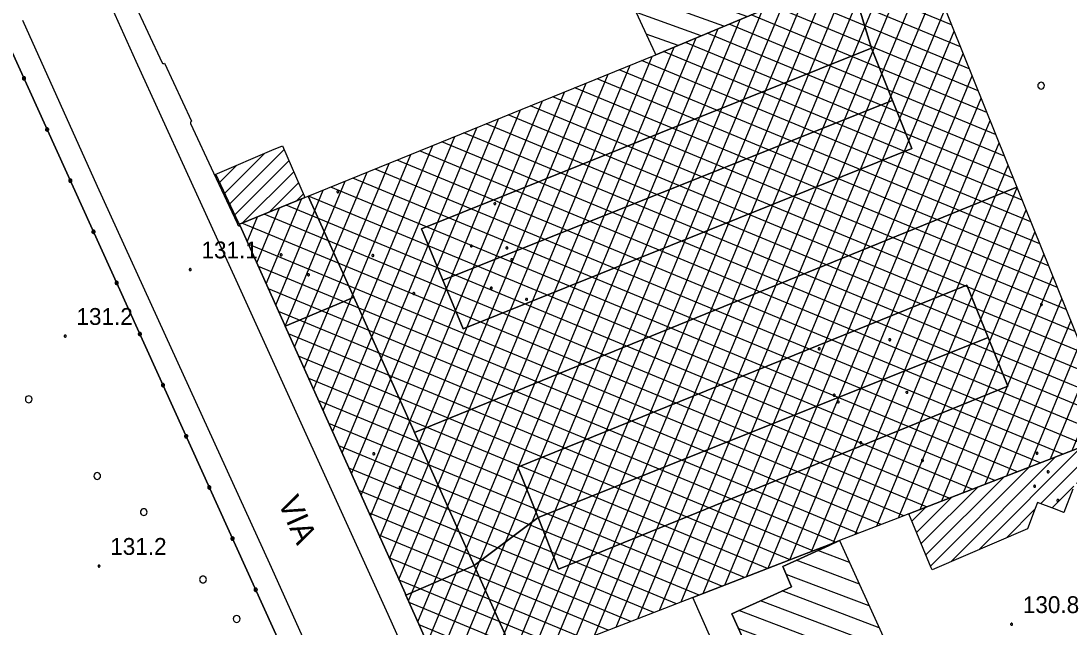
# Model space of a CAD drawing. Extents: x 513373 to 514978, y 5038576 to 5040180.
# Drawn here: x 513457.4 to 513550.7, y 5038827.3 to 5038881.2 of the extents above; entities that cross this region are included whole.
import ezdxf

# ---------------------------------------------------------------- set-up
doc = ezdxf.new("R2010")
doc.units = 0
for name, color, linetype in [('B1211', 7, 'Continuous'), ('C1131', 7, 'Continuous'), ('C12211', 7, 'Continuous'), ('C1228', 7, 'Continuous'), ('C21111', 7, 'Continuous'), ('C211113', 7, 'Continuous'), ('C21195', 7, 'Continuous'), ('C2911', 7, 'Continuous'), ('CAMP_C12211', 7, 'Continuous'), ('CAMP_C1228', 7, 'Continuous'), ('CAMP_C21111', 7, 'Continuous'), ('CAMP_C21195', 7, 'Continuous'), ('Default', 7, 'Continuous'), ('F12107', 7, 'Continuous'), ('F12131', 7, 'Continuous'), ('F12132', 7, 'Continuous'), ('G4315', 7, 'Continuous'), ('TOP500', 7, 'Continuous'), ('TOP920', 7, 'Continuous')]:
    doc.layers.add(name, color=color, linetype=linetype)

# ---------------------------------------------------------------- blocks, each defined once
blk = doc.blocks.new('CAMP_172EE3B1')
at = {"layer": 'CAMP_C1228'}
for p, q in [((-4.116, -26.219), (20.728, 33.759)), ((-6.049, -26.968), (18.763, 32.934)), ((21.465, 32.505), (19.59, 33.281)), ((-7.983, -27.718), (16.798, 32.11)), ((-2.182, -25.47), (21.646, 32.055)), ((22.251, 30.556), (17.643, 32.464)), ((-9.917, -28.467), (14.833, 31.285)), ((23.823, 26.658), (13.749, 30.83)), ((23.037, 28.607), (15.696, 31.647)), ((-11.851, -29.216), (12.867, 30.46)), ((-0.248, -24.721), (22.447, 30.069)), ((24.609, 24.708), (11.802, 30.013)), ((-13.785, -29.965), (10.902, 29.635)), ((25.394, 22.759), (9.855, 29.196)), ((-15.766, -30.829), (8.937, 28.811)), ((1.686, -23.971), (23.248, 28.083)), ((26.18, 20.81), (7.908, 28.379)), ((-19.779, -32.677), (5.007, 27.161)), ((-17.773, -31.753), (6.972, 27.986)), ((26.966, 18.861), (5.961, 27.562)), ((-21.185, -32.152), (3.041, 26.336)), ((27.752, 16.912), (4.014, 26.745)), ((-22.028, -30.267), (1.076, 25.512)), ((28.538, 14.963), (2.067, 25.927)), ((3.62, -23.222), (24.049, 26.097)), ((-22.871, -28.382), (-0.889, 24.687)), ((30.11, 11.065), (-1.827, 24.293)), ((29.324, 13.014), (0.12, 25.11)), ((-23.714, -26.497), (-2.852, 23.867)), ((30.896, 9.116), (-3.794, 23.484)), ((5.554, -22.473), (24.85, 24.111)), ((-24.557, -24.612), (-4.805, 23.073)), ((31.681, 7.167), (-5.771, 22.68)), ((-26.245, -20.85), (-8.71, 21.484)), ((-25.401, -22.73), (-6.757, 22.279)), ((32.467, 5.217), (-7.749, 21.875)), ((7.488, -21.723), (25.65, 22.124)), ((-27.09, -18.969), (-10.662, 20.69)), ((33.253, 3.268), (-9.726, 21.071)), ((-27.934, -17.088), (-12.615, 19.896)), ((34.039, 1.319), (-11.704, 20.267)), ((9.422, -20.974), (26.451, 20.138)), ((-28.779, -15.207), (-14.568, 19.102)), ((34.825, -0.63), (-13.681, 19.462)), ((-29.623, -13.326), (-16.52, 18.307)), ((36.396, -4.528), (-17.637, 17.853)), ((35.61, -2.579), (-15.659, 18.658)), ((11.356, -20.225), (27.252, 18.152)), ((-30.468, -11.445), (-18.473, 17.513)), ((37.182, -6.477), (-19.614, 17.049)), ((-32.157, -7.683), (-22.378, 15.924)), ((-31.312, -9.564), (-20.425, 16.719)), ((37.968, -8.426), (-21.592, 16.244)), ((13.29, -19.475), (28.053, 16.166)), ((-33.001, -5.802), (-24.331, 15.13)), ((37.8, -9.98), (-23.569, 15.44)), ((-33.846, -3.921), (-26.283, 14.336)), ((35.775, -10.765), (-25.547, 14.635)), ((15.224, -18.726), (28.854, 14.179)), ((-34.69, -2.04), (-28.236, 13.542)), ((33.75, -11.55), (-27.524, 13.831)), ((-35.535, -0.159), (-30.188, 12.747)), ((29.699, -13.119), (-31.48, 12.222)), ((31.724, -12.334), (-29.502, 13.026)), ((17.158, -17.977), (29.655, 12.193)), ((-36.38, 1.719), (-32.141, 11.953)), ((27.673, -13.904), (-33.457, 11.418)), ((-38.071, 5.476), (-36.046, 10.364)), ((-37.226, 3.598), (-34.094, 11.159)), ((25.648, -14.688), (-35.435, 10.613)), ((-38.917, 7.354), (-37.999, 9.57)), ((23.623, -15.473), (-37.412, 9.809)), ((19.092, -17.228), (30.456, 10.207)), ((21.597, -16.257), (-39.39, 9.004)), ((21.026, -16.479), (31.256, 8.22)), ((19.572, -17.042), (-38.822, 7.146)), ((22.96, -15.73), (32.057, 6.234)), ((17.546, -17.827), (-37.924, 5.15)), ((24.893, -14.98), (32.858, 4.248)), ((15.521, -18.611), (-37.026, 3.154)), ((26.827, -14.231), (33.659, 2.261)), ((13.495, -19.396), (-36.128, 1.159)), ((28.761, -13.482), (34.46, 0.275)), ((11.47, -20.181), (-35.231, -0.837)), ((30.695, -12.733), (35.261, -1.711)), ((9.445, -20.965), (-34.335, -2.831)), ((32.629, -11.984), (36.061, -3.697)), ((7.419, -21.75), (-33.44, -4.826)), ((34.563, -11.234), (36.862, -5.684)), ((5.394, -22.535), (-32.544, -6.82)), ((36.497, -10.485), (37.663, -7.67)), ((3.369, -23.319), (-31.649, -8.815)), ((38.431, -9.736), (38.464, -9.656)), ((1.344, -24.104), (-30.753, -10.809)), ((-0.682, -24.889), (-29.858, -12.804)), ((-2.707, -25.673), (-28.962, -14.798)), ((-4.732, -26.458), (-28.067, -16.793)), ((-6.758, -27.243), (-27.171, -18.787)), ((-8.783, -28.027), (-26.276, -20.782)), ((-10.808, -28.812), (-25.38, -22.776)), ((-12.834, -29.597), (-24.486, -24.77)), ((-14.826, -30.395), (-23.595, -26.763)), ((-16.681, -31.25), (-22.704, -28.755)), ((-18.537, -32.105), (-21.813, -30.748)), ((-20.393, -32.96), (-20.922, -32.741))]:
    blk.add_line(p, q, dxfattribs=at)
blk = doc.blocks.new('CAMP_F478D1B5')
at = {"layer": 'CAMP_C12211'}
for p, q in [((-13.389, 14.386), (-15.321, 15.082)), ((17.239, 14.519), (14.832, 15.385)), ((-12.639, 12.522), (-17.408, 14.238)), ((18.129, 12.604), (12.839, 14.509)), ((-11.889, 10.657), (-19.494, 13.395)), ((19.018, 10.69), (10.846, 13.632)), ((-11.89, 9.064), (-21.581, 12.552)), ((-13.23, 7.952), (-23.667, 11.709)), ((19.906, 8.776), (11.157, 11.926)), ((-12.368, 6.047), (-24.001, 10.235)), ((20.795, 6.862), (12.015, 10.023)), ((-11.505, 4.142), (-23.152, 8.335)), ((21.684, 4.947), (12.873, 8.12)), ((-10.643, 2.237), (-22.303, 6.435)), ((22.574, 3.033), (13.73, 6.217)), ((-9.78, 0.333), (-21.471, 4.542)), ((23.463, 1.118), (14.588, 4.313)), ((-8.918, -1.572), (-20.705, 2.671)), ((24.352, -0.796), (15.446, 2.41)), ((25.242, -2.71), (15.044, 0.961)), ((-8.055, -3.477), (-19.886, 0.782)), ((23.989, -3.854), (12.958, 0.118)), ((21.876, -4.687), (10.872, -0.726)), ((-7.193, -5.382), (-19.003, -1.13)), ((19.763, -5.521), (8.786, -1.569)), ((17.65, -6.354), (6.7, -2.412)), ((-6.33, -7.286), (-18.12, -3.042)), ((15.537, -7.188), (4.615, -3.256)), ((13.423, -8.021), (2.529, -4.099)), ((3.165, -12.299), (-17.237, -4.954)), ((11.344, -8.867), (0.443, -4.942)), ((9.299, -9.725), (-1.643, -5.786)), ((1.121, -13.157), (-16.353, -6.866)), ((7.255, -10.583), (-3.728, -6.629)), ((5.21, -11.441), (-5.814, -7.472)), ((-0.924, -14.016), (-15.47, -8.779)), ((-2.969, -14.874), (-14.587, -10.691)), ((-5.014, -15.732), (-13.704, -12.603)), ((-7.058, -16.59), (-12.821, -14.515)), ((-9.103, -17.448), (-11.938, -16.427))]:
    blk.add_line(p, q, dxfattribs=at)
blk = doc.blocks.new('CAMP_EDF7B2BA')
at = {"layer": 'CAMP_C12211'}
for p, q in [((-15.013, 46.563), (-15.029, 46.569)), ((-13.253, 42.69), (-18.881, 44.817)), ((-14.133, 44.627), (-16.955, 45.693)), ((-12.373, 40.754), (-19.77, 43.55)), ((-11.492, 38.818), (-20.148, 42.089)), ((-10.612, 36.882), (-22.07, 41.212)), ((-9.732, 34.946), (-23.992, 40.335)), ((-8.851, 33.01), (-24.047, 38.752)), ((-7.971, 31.074), (-23.166, 36.815)), ((-7.091, 29.137), (-22.285, 34.879)), ((-6.211, 27.201), (-21.405, 32.943)), ((-5.33, 25.265), (-20.524, 31.006)), ((-4.45, 23.329), (-19.644, 29.07)), ((-3.57, 21.393), (-18.763, 27.134)), ((-2.689, 19.457), (-17.882, 25.198)), ((-1.809, 17.521), (-17.002, 23.261)), ((-0.929, 15.584), (-16.121, 21.325)), ((-0.049, 13.648), (-15.24, 19.389)), ((0.832, 11.712), (-14.359, 17.452)), ((1.712, 9.776), (-13.479, 15.516)), ((2.592, 7.84), (-12.598, 13.58)), ((3.473, 5.904), (-11.717, 11.643)), ((4.353, 3.967), (-10.837, 9.707)), ((5.233, 2.031), (-9.956, 7.771)), ((6.113, 0.095), (-9.075, 5.834)), ((6.994, -1.841), (-8.194, 3.898)), ((7.874, -3.777), (-7.314, 1.962)), ((8.754, -5.713), (-6.433, 0.026)), ((9.635, -7.649), (-5.552, -1.911)), ((10.515, -9.586), (-4.672, -3.847)), ((11.394, -11.521), (-3.791, -5.783)), ((12.272, -13.457), (-2.91, -7.72)), ((13.15, -15.392), (-2.029, -9.656)), ((14.028, -17.327), (-1.149, -11.592)), ((14.906, -19.263), (-0.268, -13.529)), ((15.785, -21.198), (0.613, -15.465)), ((16.663, -23.133), (1.493, -17.401)), ((17.541, -25.069), (2.374, -19.338)), ((18.419, -27.004), (3.255, -21.274)), ((19.297, -28.939), (4.135, -23.21)), ((20.175, -30.874), (5.016, -25.146)), ((21.058, -32.812), (5.897, -27.083)), ((21.945, -34.75), (6.777, -29.019)), ((22.83, -36.688), (7.658, -30.955)), ((23.713, -38.625), (8.539, -32.892)), ((24.596, -40.563), (9.419, -34.828)), ((25.479, -42.5), (10.3, -36.764)), ((24.118, -43.589), (11.181, -38.7)), ((22.189, -44.464), (12.061, -40.637)), ((20.26, -45.338), (12.942, -42.573)), ((18.331, -46.213), (13.823, -44.509)), ((16.403, -47.088), (14.704, -46.446))]:
    blk.add_line(p, q, dxfattribs=at)
blk = doc.blocks.new('CAMP_2F9B1B2A')
at = {"layer": 'CAMP_C21111'}
for p, q in [((-3.433, -0.605), (0.103, 2.931)), ((-2.983, -1.568), (1.853, 3.267)), ((-3.884, 0.358), (-2.359, 1.884)), ((-2.532, -2.532), (2.277, 2.277)), ((-1.857, -3.271), (2.701, 1.287)), ((0.527, -2.301), (3.125, 0.297)), ((2.911, -1.331), (3.55, -0.693))]:
    blk.add_line(p, q, dxfattribs=at)
blk = doc.blocks.new('CAMP_9FC88B0B')
at = {"layer": 'CAMP_C21195'}
for p, q in [((7.267, 1.118), (14.947, 8.798)), ((8.795, 1.232), (16.636, 9.073)), ((6.252, 1.517), (12.544, 7.809)), ((11.261, 2.284), (17.1, 8.122)), ((3.079, -0.241), (10.141, 6.82)), ((13.728, 3.336), (17.563, 7.171)), ((2.062, 0.156), (7.737, 5.831)), ((16.194, 4.389), (18.026, 6.221)), ((-1.174, -1.666), (5.334, 4.842)), ((-2.191, -1.269), (2.931, 3.853)), ((-5.38, -3.043), (0.56, 2.896)), ((-10.906, -7.155), (-1.749, 2.002)), ((-13.386, -8.221), (-4.057, 1.108)), ((-15.192, -8.613), (-6.366, 0.213)), ((-15.608, -7.614), (-8.674, -0.681)), ((-0.158, -2.064), (1.149, -0.757)), ((4.096, -0.639), (4.402, -0.332)), ((-16.023, -6.616), (-10.983, -1.575)), ((-4.362, -3.44), (-2.421, -1.498)), ((-16.439, -5.617), (-13.292, -2.47)), ((-16.854, -4.618), (-15.6, -3.364)), ((-8.427, -6.09), (-5.895, -3.558)), ((-3.344, -3.836), (-3.322, -3.814))]:
    blk.add_line(p, q, dxfattribs=at)
blk = doc.blocks.new('03080200')
at = {"layer": 'Default'}
for p, q in [((-0.139, 0.046), (-0.146, 0)), ((-0.146, 0), (-0.139, -0.046)), ((-0.118, 0.086), (-0.139, 0.046)), ((-0.086, 0.118), (-0.118, 0.086)), ((-0.046, 0.139), (-0.086, 0.118)), ((0, 0.146), (-0.046, 0.139)), ((-0.042, 0.014), (-0.045, 0)), ((-0.045, 0), (-0.042, -0.014)), ((-0.036, 0.026), (-0.042, 0.014)), ((-0.026, 0.036), (-0.036, 0.026)), ((-0.014, 0.042), (-0.026, 0.036)), ((0, 0.045), (-0.014, 0.042)), ((0.046, 0.139), (0, 0.146)), ((0.014, 0.042), (0, 0.045)), ((0.026, 0.036), (0.014, 0.042)), ((0.036, 0.026), (0.026, 0.036)), ((0.042, 0.014), (0.036, 0.026)), ((0.045, 0), (0.042, 0.014)), ((0.042, -0.014), (0.045, 0)), ((0.086, 0.118), (0.046, 0.139)), ((0.118, 0.086), (0.086, 0.118)), ((0.139, 0.046), (0.118, 0.086)), ((0.146, 0), (0.139, 0.046)), ((0.139, -0.046), (0.146, 0)), ((-0.139, -0.046), (-0.118, -0.086)), ((-0.118, -0.086), (-0.086, -0.118)), ((-0.086, -0.118), (-0.046, -0.139)), ((-0.046, -0.139), (0, -0.146)), ((-0.042, -0.014), (-0.036, -0.026)), ((-0.036, -0.026), (-0.026, -0.036)), ((-0.026, -0.036), (-0.014, -0.042)), ((-0.014, -0.042), (0, -0.045)), ((0, -0.045), (0.014, -0.042)), ((0, -0.146), (0.046, -0.139)), ((0.014, -0.042), (0.026, -0.036)), ((0.026, -0.036), (0.036, -0.026)), ((0.036, -0.026), (0.042, -0.014)), ((0.046, -0.139), (0.086, -0.118)), ((0.086, -0.118), (0.118, -0.086)), ((0.118, -0.086), (0.139, -0.046))]:
    blk.add_line(p, q, dxfattribs=at)
blk = doc.blocks.new('08020400')
at = {"layer": 'Default'}
for p, q in [((-0.086, 0.028), (-0.09, 0)), ((-0.09, 0), (-0.086, -0.028)), ((-0.073, 0.053), (-0.086, 0.028)), ((-0.053, 0.073), (-0.073, 0.053)), ((-0.028, 0.086), (-0.053, 0.073)), ((0, 0.09), (-0.028, 0.086)), ((0.028, 0.086), (0, 0.09)), ((0.053, 0.073), (0.028, 0.086)), ((0.073, 0.053), (0.053, 0.073)), ((0.086, 0.028), (0.073, 0.053)), ((0.09, 0), (0.086, 0.028)), ((0.086, -0.028), (0.09, 0)), ((-0.086, -0.028), (-0.073, -0.053)), ((-0.073, -0.053), (-0.053, -0.073)), ((-0.053, -0.073), (-0.028, -0.086)), ((-0.028, -0.086), (0, -0.09)), ((0, -0.09), (0.028, -0.086)), ((0.028, -0.086), (0.053, -0.073)), ((0.053, -0.073), (0.073, -0.053)), ((0.073, -0.053), (0.086, -0.028))]:
    blk.add_line(p, q, dxfattribs=at)
blk = doc.blocks.new('NSIMB25')
at = {"layer": 'Default'}
for p, q in [((-0.086, 0.028), (-0.09, 0)), ((-0.09, 0), (-0.086, -0.028)), ((-0.073, 0.053), (-0.086, 0.028)), ((-0.053, 0.073), (-0.073, 0.053)), ((-0.028, 0.086), (-0.053, 0.073)), ((0, 0.09), (-0.028, 0.086)), ((0.028, 0.086), (0, 0.09)), ((0.053, 0.073), (0.028, 0.086)), ((0.073, 0.053), (0.053, 0.073)), ((0.086, 0.028), (0.073, 0.053)), ((0.09, 0), (0.086, 0.028)), ((0.086, -0.028), (0.09, 0)), ((-0.086, -0.028), (-0.073, -0.053)), ((-0.073, -0.053), (-0.053, -0.073)), ((-0.053, -0.073), (-0.028, -0.086)), ((-0.028, -0.086), (0, -0.09)), ((0, -0.09), (0.028, -0.086)), ((0.028, -0.086), (0.053, -0.073)), ((0.053, -0.073), (0.073, -0.053)), ((0.073, -0.053), (0.086, -0.028))]:
    blk.add_line(p, q, dxfattribs=at)
blk = doc.blocks.new('05010100')
at = {"layer": 'Default'}
for p, q in [((-0.143, 0.046), (-0.15, 0)), ((-0.15, 0), (-0.143, -0.046)), ((-0.121, 0.088), (-0.143, 0.046)), ((-0.088, 0.121), (-0.121, 0.088)), ((-0.046, 0.143), (-0.088, 0.121)), ((0, 0.15), (-0.046, 0.143)), ((0.046, 0.143), (0, 0.15)), ((0.088, 0.121), (0.046, 0.143)), ((0.121, 0.088), (0.088, 0.121)), ((0.143, 0.046), (0.121, 0.088)), ((0.15, 0), (0.143, 0.046)), ((0.143, -0.046), (0.15, 0)), ((-0.143, -0.046), (-0.121, -0.088)), ((-0.121, -0.088), (-0.088, -0.121)), ((-0.088, -0.121), (-0.046, -0.143)), ((-0.046, -0.143), (0, -0.15)), ((0, -0.15), (0.046, -0.143)), ((0.046, -0.143), (0.088, -0.121)), ((0.088, -0.121), (0.121, -0.088)), ((0.121, -0.088), (0.143, -0.046))]:
    blk.add_line(p, q, dxfattribs=at)
blk = doc.blocks.new('A$C3704598A')
at = {"layer": 'B1211'}
for points in [[(94.332, -497.179), (96.884, -502.628), (96.906, -502.655), (96.928, -502.673), (96.958, -502.689), (96.996, -502.697), (97.04, -502.695), (97.092, -502.672), (99.515, -507.84), (99.47, -507.86), (99.448, -507.878), (99.425, -507.907), (99.408, -507.95), (99.405, -507.991), (99.412, -508.034), (101.471, -512.434), (103.57, -516.919), (103.647, -517.084), (103.671, -517.116), (103.693, -517.134), (103.718, -517.148), (103.754, -517.158), (103.796, -517.159), (103.829, -517.15), (107.782, -525.934), (107.855, -526.094), (118.525, -549.862), (118.602, -550.033), (122.549, -558.859)], [(178.888, -672.206), (176.406, -672.89), (176.1, -672.93), (175.755, -672.975), (174.978, -672.987), (174.361, -672.84), (173.877, -672.725), (172.726, -672.083), (172.349, -671.829), (171.665, -671.369), (170.95, -670.389), (170.541, -669.571), (168.285, -664.691), (160.651, -647.821), (151.346, -627.269), (142.537, -607.914), (132.751, -586.689), (123.465, -566.119), (117.038, -551.754), (103.489, -521.985), (94.591, -502.503), (88.175, -488.246)], [(84.441, -498.839), (91.117, -513.605), (97.67, -527.991), (106.443, -547.22), (113.013, -561.806), (120.311, -577.932), (126.473, -591.555), (135.3, -610.767), (143.131, -628.055), (149.774, -642.531), (159.201, -663.609)], [(107.579, -554.75), (79.354, -492.478)]]:
    blk.add_lwpolyline(points, dxfattribs=at)
at = {"layer": 'C1131'}
for points in [[(155.193, -487.453), (158.003, -494.541), (158.068, -494.703), (140.87, -501.921), (140.797, -501.763), (131.673, -482.009), (130.32, -478.708), (137.562, -475.638), (138.515, -475.234), (145.707, -491.116), (145.773, -491.262), (154.226, -487.844)], [(173.024, -513.695), (172.06, -514.088), (119.367, -535.569), (119.3, -535.42), (113.956, -523.518), (109.914, -514.514), (140.87, -501.921), (158.068, -494.703), (160.07, -501.317), (159.103, -501.706), (119.99, -517.43), (121.835, -521.849), (121.895, -521.993), (123.64, -526.173), (123.701, -526.319), (163.663, -510.254), (161.95, -505.992), (160.07, -501.317), (158.068, -494.703), (163.35, -492.487), (164.311, -492.083)], [(161.95, -505.992), (160.982, -506.379), (121.895, -521.993), (121.835, -521.849), (119.99, -517.43), (159.103, -501.706), (160.07, -501.317)], [(121.895, -521.993), (160.982, -506.379), (161.95, -505.992), (163.663, -510.254), (123.701, -526.319), (123.64, -526.173)], [(109.597, -514.643), (108.955, -514.904), (103.776, -517.01), (103.707, -516.864), (101.683, -512.537), (101.822, -512.478), (106.659, -510.421), (107.614, -510.015), (109.533, -514.494)], [(113.956, -523.518), (113.003, -523.92), (107.855, -526.094), (107.782, -525.934), (103.829, -517.15), (103.776, -517.01), (108.955, -514.904), (109.597, -514.643), (109.914, -514.514)], [(170.472, -527.1), (169.506, -527.486), (130.376, -543.13), (130.318, -542.985), (128.587, -538.643), (167.613, -522.828), (168.577, -522.438)], [(119.367, -535.569), (124.673, -547.391), (123.726, -547.803), (118.602, -550.033), (118.525, -549.862), (107.855, -526.094), (113.003, -523.92), (113.956, -523.518), (119.3, -535.42)], [(130.376, -543.13), (169.506, -527.486), (170.472, -527.1), (172.236, -531.439), (132.21, -547.735), (132.15, -547.583)], [(183.231, -602.351), (182.295, -602.784), (172.843, -607.161), (172.755, -606.967), (153.975, -565.678), (147.624, -551.714), (152.947, -549.285), (152.179, -547.483), (156.299, -545.61), (157.239, -545.182)], [(128.661, -556.274), (122.784, -558.981), (122.648, -559.044), (122.574, -558.915), (122.549, -558.859), (118.602, -550.033), (123.726, -547.803), (124.673, -547.391), (128.594, -556.124)]]:
    blk.add_lwpolyline(points, close=True, dxfattribs=at)
for points in [[(181.872, -535.64), (163.401, -542.795), (162.432, -543.171), (157.239, -545.182), (156.274, -545.556), (153.887, -546.481), (144.154, -550.252), (128.923, -556.153)], [(128.594, -556.124), (124.673, -547.391), (130.376, -543.13), (132.15, -547.583), (132.21, -547.735), (172.236, -531.439), (170.472, -527.1), (168.577, -522.438), (167.613, -522.828), (128.587, -538.643), (130.318, -542.985), (130.376, -543.13), (124.673, -547.391), (119.367, -535.569), (172.06, -514.088), (173.024, -513.695), (181.809, -535.484)], [(178.001, -540.616), (177.198, -542.68), (176.389, -542.364), (174.878, -541.776), (174.662, -542.331), (173.96, -544.132), (165.474, -547.777), (165.403, -547.608), (163.401, -542.795), (181.872, -535.64)]]:
    blk.add_lwpolyline(points, dxfattribs=at)
at = {"layer": 'C12211'}
blk.add_lwpolyline([(158.068, -494.703), (140.87, -501.921), (140.797, -501.763), (131.673, -482.009)], dxfattribs=at)
blk.add_lwpolyline([(197.915, -634.647), (187.494, -639.373), (187.408, -639.185), (182.329, -628.018), (182.246, -627.836), (172.843, -607.161), (172.755, -606.967), (153.975, -565.678), (147.624, -551.714), (152.947, -549.285), (152.179, -547.483), (156.299, -545.61), (157.239, -545.182), (183.231, -602.351), (192.763, -623.359), (194.725, -627.649), (195.345, -629.01), (197.829, -634.459)], close=True, dxfattribs=at)
at = {"layer": 'C1228'}
for points in [[(164.311, -492.083), (173.024, -513.695), (181.809, -535.484)], [(181.872, -535.64), (163.401, -542.795), (162.432, -543.171), (157.239, -545.182), (156.274, -545.556), (153.887, -546.481), (144.154, -550.252), (128.923, -556.153), (128.661, -556.274), (122.784, -558.981), (122.648, -559.044), (122.574, -558.915), (122.549, -558.859), (118.602, -550.033), (118.525, -549.862), (107.855, -526.094), (107.782, -525.934), (103.829, -517.15), (103.776, -517.01), (108.955, -514.904), (109.597, -514.643), (109.914, -514.514), (140.87, -501.921), (158.068, -494.703)]]:
    blk.add_lwpolyline(points, dxfattribs=at)
at = {"layer": 'C21111'}
blk.add_lwpolyline([(109.597, -514.643), (108.955, -514.904), (103.776, -517.01), (103.707, -516.864), (101.683, -512.537), (101.822, -512.478), (106.659, -510.421), (107.614, -510.015), (109.533, -514.494)], close=True, dxfattribs=at)
at = {"layer": 'C211113'}
blk.add_lwpolyline([(144.154, -550.252), (153.887, -546.481), (156.274, -545.556), (157.239, -545.182), (156.299, -545.61), (152.179, -547.483), (152.947, -549.285), (147.624, -551.714), (153.975, -565.678), (153.033, -566.102), (151.483, -566.799)], close=True, dxfattribs=at)
at = {"layer": 'C21195'}
blk.add_lwpolyline([(178.001, -540.616), (177.198, -542.68), (176.389, -542.364), (174.878, -541.776), (174.662, -542.331), (173.96, -544.132), (165.474, -547.777), (165.403, -547.608), (163.401, -542.795), (181.872, -535.64)], dxfattribs=at)
at = {"layer": 'C2911'}
blk.add_lwpolyline([(70.227, -496.128), (78.393, -492.862), (79.354, -492.478), (107.579, -554.75)], dxfattribs=at)
at = {"layer": 'C2911', "rotation": -65.61747928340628}
for p in [(84.585, -504.018), (86.649, -508.572), (88.713, -513.126), (90.777, -517.68), (92.841, -522.234), (94.905, -526.789), (96.97, -531.343), (99.034, -535.897), (101.098, -540.451), (103.162, -545.005), (105.226, -549.559)]:
    blk.add_blockref('03080200', p, dxfattribs=at)
at = {"layer": 'CAMP_C12211'}
for name, p in [('CAMP_F478D1B5', (151.952, -483.642)), ('CAMP_EDF7B2BA', (172.258, -591.756))]:
    blk.add_blockref(name, p, dxfattribs=at)
at = {"layer": 'CAMP_C1228'}
blk.add_blockref('CAMP_172EE3B1', (143.385, -525.925), dxfattribs=at)
at = {"layer": 'CAMP_C21111'}
blk.add_blockref('CAMP_2F9B1B2A', (105.909, -513.627), dxfattribs=at)
at = {"layer": 'CAMP_C21195'}
blk.add_blockref('CAMP_9FC88B0B', (180.531, -538.839), dxfattribs=at)
at = {"layer": 'F12107'}
for p in [(99.394, -521.049), (88.259, -526.974), (91.269, -547.451), (172.558, -552.636)]:
    blk.add_blockref('08020400', p, dxfattribs=at)
at = {"layer": 'F12131'}
for p in [(124.432, -518.948), (115.665, -519.794), (109.93, -521.513), (126.212, -522.695), (161.709, -527.294), (163.235, -531.977), (164.617, -538.045), (118.09, -540.441), (174.611, -540.339)]:
    blk.add_blockref('NSIMB25', p, dxfattribs=at)
at = {"layer": 'F12132'}
for p in [(112.545, -514.113), (126.526, -515.175), (127.606, -519.121), (107.485, -519.734), (128.038, -520.167), (119.305, -523.177), (129.352, -523.698), (175.207, -524.161), (155.419, -528.1), (156.752, -532.234), (157.118, -532.839), (159.127, -536.468), (115.746, -537.449), (174.823, -537.407), (175.805, -539.053), (176.679, -541.607)]:
    blk.add_blockref('NSIMB25', p, dxfattribs=at)
at = {"layer": 'G4315', "xscale": 2, "yscale": 2}
for p in [(175.185, -504.669), (85.007, -532.6), (91.112, -539.431), (95.252, -542.64), (100.531, -548.643), (103.532, -552.162)]:
    blk.add_blockref('05010100', p, dxfattribs=at)
at = {"layer": 'TOP500'}
blk.add_text('VIA', height=2, rotation=294.10207, dxfattribs=at).set_placement((107.161, -541.747))
at = {"layer": 'TOP920'}
for s, p in [('131.1', (100.394, -520.049)), ('131.2', (89.259, -525.974)), ('131.2', (92.269, -546.451)), ('130.8', (173.558, -551.636))]:
    blk.add_text(s, height=1.5, dxfattribs=at).set_placement(p)

msp = doc.modelspace()

# ---------------------------------------------------------------- block references
at = {"layer": 'Default'}
msp.add_blockref('A$C3704598A', (513373.046, 5039380.14), dxfattribs=at)

doc.saveas('drawing.dxf')
